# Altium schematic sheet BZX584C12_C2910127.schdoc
size 127 x 101 mm
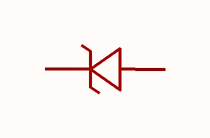
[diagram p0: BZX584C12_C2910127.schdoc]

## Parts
D?  bzx584c12_c2910127  [SOD-523_L1.2-W0.8-LS1.6-RD]  (value not drawn)

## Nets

Not connected (* = marked no-connect by the designer): D? 1(K) 2(A)

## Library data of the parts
D? = bzx584c12_c2910127: 二极管配置:1个独立式;稳压值(标称值):12V;稳压值(范围):11.4V~12.7V;耗散功率(Pd):150mW;; Manufacturer: CJ(江苏长电/长晶); AddInBom: yes; ModelId: 8f56a03db567494d8f4c9d12aa52a741; ModelName: SOD-523_L1.2-W0.8-H0.7-LS1.6; ModelTransform: 62.992,31.496,0,180,0,0,0,0,0; Diode Configuration: 1个独立式; Zener Voltage(Nom): 12V; Reverse Leakage Current (Ir): 100nA@8V; Pd - Power Dissipation: 150mW; Impedance(Zzt): 25Ω; Impedance(Zzk): 150Ω; Operating Junction Temperature Range: -55℃~+150℃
